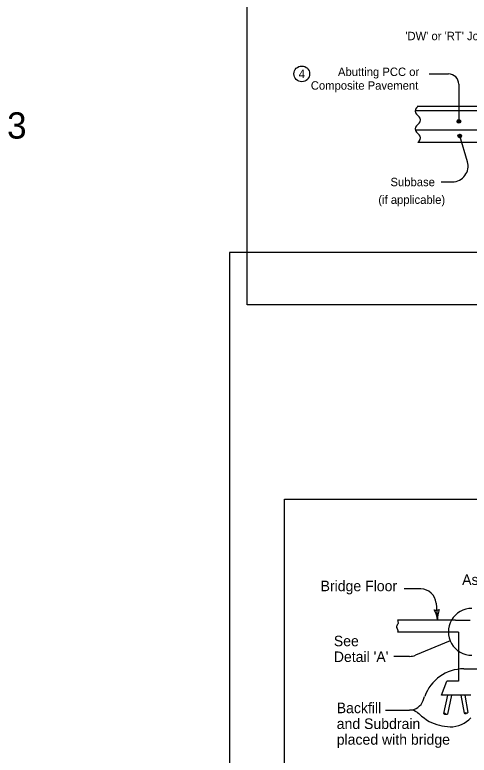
# Model space of a CAD drawing. Extents: x 10130 to 81668, y 5440 to 21644.
# Drawn here: x 13290 to 14155, y 7067 to 8476 of the extents above; entities that cross this region are included whole.
import ezdxf

# ---------------------------------------------------------------- set-up
doc = ezdxf.new("R2010")
doc.units = 0
for name, color, linetype in [('Cell', 7, 'Continuous'), ('dsnShtPlotShapeBatchPrint', 7, 'Continuous'), ('dsnStdBlock', 7, 'Continuous'), ('dsnStdBlockModified', 7, 'Continuous'), ('dsnStdBlockNotModified', 7, 'Continuous'), ('dsnStdBorder', 7, 'Continuous'), ('dsnStdLabel', 7, 'Continuous'), ('Level 2', 7, 'Continuous'), ('SheetBorder', 7, 'Continuous')]:
    doc.layers.add(name, color=color, linetype=linetype)

msp = doc.modelspace()

# ---------------------------------------------------------------- linework, layer by layer
at = {"layer": 'Cell'}
msp.add_lwpolyline([(13803.2, 7554.1), (16938.2, 7554.1), (16938.2, 5544.1), (13803.2, 5544.1)], close=True, dxfattribs=at)
at = {"layer": 'dsnShtPlotShapeBatchPrint'}
msp.add_lwpolyline([(13698.7, 5439.6), (17042.7, 5439.6), (17042.7, 8023.6), (13698.7, 8023.6)], close=True, dxfattribs=at)
at = {"layer": 'dsnStdBlock'}
for p, q in [((14227.9, 8301.3), (14056.2, 8301.3)), ((14227.9, 8293.3), (14052.2, 8293.3)), ((14053.2, 8256.8), (14227.9, 8256.8)), ((14227.9, 8233), (14057.2, 8233))]:
    msp.add_line(p, q, dxfattribs=at)
at = {"layer": 'dsnStdBlockModified'}
for p, q in [((14091.9, 7356.4), (14094.8, 7323.9)), ((14118.9, 7284.6), (14052.7, 7257.2)), ((14041.4, 7255), (14011.4, 7255)), ((14144.8, 7231.3), (14170.5, 7231.3)), ((14067.5, 7171.3), (14070.2, 7178.8)), ((13995.7, 7152.9), (14041.4, 7152.9))]:
    msp.add_line(p, q, dxfattribs=at)
for centre, radius, start, end in [((14160.1, 7301.6), 44.6, 89.9996, 270), ((14041.4, 7284.7), 29.7, 270, 292.4496), ((14167.8, 7268.3), 163.6, 227.1442, 236.9942), ((14127.7, 7239), 118.5, 245.5915, 265.546), ((14118.2, 7175.8), 55, 270.3325, 316.7198)]:
    msp.add_arc(centre, radius, start, end, dxfattribs=at)
at = {"layer": 'dsnStdBlockNotModified'}
for p, q in [((14079, 8363.3), (14115.4, 8363.3)), ((14135.2, 8343.5), (14135.2, 8272.3)), ((14151.6, 8196.2), (14137, 8245.2)), ((14101.4, 8158), (14123.1, 8158))]:
    msp.add_line(p, q, dxfattribs=at)
for points in [[(14132.1, 8272.6), (14132.6, 8273.8), (14133.2, 8275.6), (14135, 8276), (14136.7, 8275.7), (14138.2, 8274.5), (14138, 8272.8), (14137.7, 8271), (14136.3, 8270.1), (14134.8, 8270), (14132.8, 8271), (14132.6, 8272.4), (14133, 8274.2), (14134.2, 8275.7), (14135.9, 8275.6), (14137.3, 8274.5), (14137.5, 8272.8), (14137.1, 8271), (14136.1, 8270.7), (14134.9, 8270.4), (14133.4, 8271.2), (14133.4, 8272.5), (14133.7, 8274.1), (14134.5, 8275.2), (14136, 8274.6), (14136.9, 8273.5), (14136.9, 8271.9), (14136.1, 8271.6), (14135.2, 8271.1), (14134, 8271.8), (14133.7, 8272.9), (14134.3, 8273.9), (14135.4, 8274), (14136.2, 8273.5), (14136.5, 8272.5), (14136, 8272), (14135.4, 8271.7), (14134.5, 8272.2), (14134.3, 8272.9), (14134.8, 8273.6), (14135.4, 8273.5), (14135.8, 8273), (14135.7, 8272.3), (14135.2, 8272.3), (14134.9, 8272.9)], [(14136.7, 8248.4), (14137.9, 8247.8), (14139.7, 8247.3), (14140.1, 8245.4), (14139.8, 8243.8), (14138.7, 8242.3), (14136.9, 8242.5), (14135.1, 8242.7), (14134.2, 8244.2), (14134.1, 8245.7), (14135.1, 8247.7), (14136.5, 8247.9), (14138.3, 8247.4), (14139.8, 8246.2), (14139.7, 8244.5), (14138.6, 8243.1), (14136.9, 8243), (14135.1, 8243.3), (14134.8, 8244.4), (14134.5, 8245.6), (14135.3, 8247.1), (14136.7, 8247), (14138.2, 8246.8), (14139.3, 8246), (14138.7, 8244.4), (14137.6, 8243.6), (14136, 8243.5), (14135.7, 8244.3), (14135.2, 8245.3), (14135.9, 8246.5), (14137.1, 8246.7), (14138.1, 8246.2), (14138.1, 8245.1), (14137.6, 8244.3), (14136.6, 8244), (14136.1, 8244.4), (14135.8, 8245), (14136.3, 8245.9), (14137, 8246.1), (14137.7, 8245.7), (14137.6, 8245.1), (14137.1, 8244.7), (14136.4, 8244.7), (14136.4, 8245.2), (14137, 8245.5)]]:
    msp.add_lwpolyline(points, dxfattribs=at)
for centre in [(14135.3, 8272.9), (14137, 8245.2)]:
    msp.add_circle(centre, 3.47, dxfattribs=at)
for centre, radius, start, end in [((14115.4, 8343.5), 19.8, 0, 90), ((14123.1, 8187.7), 29.7, 270, 16.5828), ((14091.7, 7359.4), 16.4, 257.2333, 292.7), ((14052.4, 7320.2), 42.5, 4.9667, 33.0392), ((14137.1, 7327.5), 42.5, 156.8942, 184.9667)]:
    msp.add_arc(centre, radius, start, end, dxfattribs=at)
at = {"layer": 'dsnStdBorder'}
for p, q in [((14054.7, 8298.7), (14057.2, 8301.2)), ((14059.7, 8281.7), (14054.7, 8286.7)), ((14057.2, 8267.1), (14059.7, 8269.6)), ((14054.7, 8264.6), (14057.2, 8267.1)), ((14059.7, 8247.6), (14054.7, 8252.5)), ((14057.2, 8233), (14059.7, 8235.5)), ((14062.8, 7383.5), (14031.1, 7383.5)), ((14128.9, 7323.9), (14018.3, 7323.9)), ((14128.9, 7323.9), (14157.1, 7323.9)), ((14134.8, 7300.9), (14018.3, 7300.9)), ((14134.8, 7300.9), (14134.8, 7208)), ((14102.2, 7181.3), (14112.4, 7208)), ((14134.8, 7208), (14112.4, 7208)), ((14158.1, 7181.3), (14102.2, 7181.3)), ((14113.6, 7181.3), (14106.1, 7146.5)), ((14121.2, 7181.3), (14113.4, 7144.9)), ((14138.9, 7181.3), (14145.2, 7147)), ((14146.4, 7181.3), (14152.5, 7148.3))]:
    msp.add_line(p, q, dxfattribs=at)
for centre, radius, start, end in [((14060.7, 8292.7), 8.53, 135, 225), ((14053.7, 8275.6), 8.53, 315, 45), ((14060.7, 8258.6), 8.53, 135, 225), ((14053.7, 8241.5), 8.53, 315, 45), ((14062.4, 7353.8), 29.7, 4.9696, 89.1065), ((14144.8, 7152.1), 79.2, 90, 160.3012), ((14041.4, 7180.6), 27.7, 270, 340.3019), ((14041.4, 7125.2), 27.7, 56.8248, 90)]:
    msp.add_arc(centre, radius, start, end, dxfattribs=at)
for points in [[(14018.3, 7323.9), (14019.5, 7317.9), (14016.5, 7311.9), (14019.2, 7304.3), (14018.8, 7300.9)], [(14106.1, 7146.5), (14109.2, 7146.8), (14111, 7145.1), (14113.4, 7144.9)], [(14106.1, 7146.5), (14108.2, 7145), (14110.7, 7145.2)], [(14145.2, 7147), (14148, 7148.1), (14150.8, 7146.9), (14152.5, 7148.3)], [(14145.2, 7147), (14147.9, 7146), (14150, 7146.9)]]:
    msp.add_spline(points, degree=3, dxfattribs=at)
at = {"layer": 'Level 2'}
msp.add_circle((13836.3, 8363.3), 15, dxfattribs=at)
at = {"layer": 'SheetBorder'}
msp.add_lwpolyline([(13732.5, 9944), (16867.5, 9944), (16867.5, 7924), (13732.5, 7924)], close=True, dxfattribs=at)

# ---------------------------------------------------------------- texts
at = {"layer": 'dsnStdBlockModified'}
for s, p in [('As required by skew angle (20\'-0" min.)', (14141.5, 7390.9)), ('Bridge Floor', (13872.1, 7379)), ('See', (13897.3, 7274.3)), ("Detail 'A'", (13897.3, 7244.3)), ('Backfill', (13902.8, 7146.9)), ('and Subdrain', (13902.8, 7116.9)), ('placed with bridge', (13902.8, 7086.9))]:
    msp.add_text(s, height=20, dxfattribs=at).set_placement(p)
at = {"layer": 'dsnStdBlockNotModified'}
for s, p in [("'DW' or 'RT' Joint", (14033.4, 8427.4)), ('Abutting PCC or', (13905.2, 8359.3)), ('Composite Pavement', (13853.5, 8333.3)), ('Subbase', (14005.2, 8149.6)), ('(if applicable)', (13982, 8116))]:
    msp.add_text(s, height=16, dxfattribs=at).set_placement(p)
at = {"layer": 'dsnStdLabel'}
msp.add_text('BR-203', height=50, dxfattribs=at).set_placement((13085.8, 8240.2))
at = {"layer": 'Level 2'}
msp.add_text('4', height=16, dxfattribs=at).set_placement((13830.4, 8355.3))

doc.saveas('drawing.dxf')
